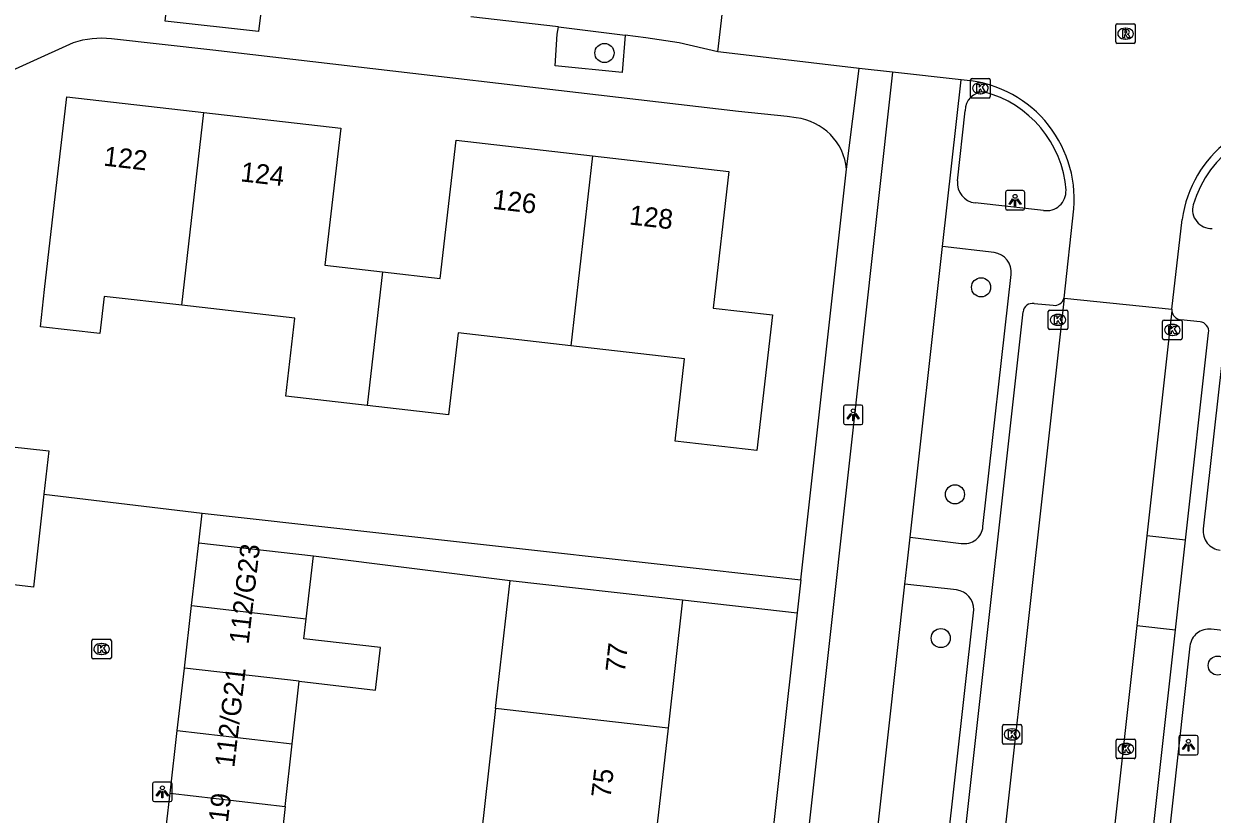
# Model space of a CAD drawing. Extents: x 162026 to 163499, y 387297 to 388169.
# Drawn here: x 162251.6 to 162312.4, y 387941.9 to 387982.3 of the extents above; entities that cross this region are included whole.
import ezdxf

# ---------------------------------------------------------------- set-up
doc = ezdxf.new("R2010")
doc.units = 0
for name, color, linetype in [('IMGEO_Boom', 7, 'Continuous'), ('IMGEO_Fietspad_gesloten', 7, 'Continuous'), ('IMGEO_Kolk', 7, 'Continuous'), ('IMGEO_Lichtpunt', 7, 'Continuous'), ('IMGEO_Pand', 7, 'Continuous'), ('IMGEO_Pand_nummerreeks', 7, 'Continuous'), ('IMGEO_Parkeervlak_open', 7, 'Continuous'), ('IMGEO_Rijbaan_lokaal_gesloten', 7, 'Continuous'), ('IMGEO_Rijbaan_lokaal_open', 7, 'Continuous'), ('IMGEO_Rioolput', 7, 'Continuous'), ('IMGEO_Voetpad_open', 7, 'Continuous')]:
    doc.layers.add(name, color=color, linetype=linetype)

msp = doc.modelspace()

# ---------------------------------------------------------------- linework, layer by layer
at = {"layer": 'IMGEO_Boom'}
for centre in [(162281.289, 387980.833), (162300.567, 387968.849), (162299.23, 387958.261), (162298.502, 387950.91), (162312.679, 387949.505)]:
    msp.add_circle(centre, 0.489, dxfattribs=at)
at = {"layer": 'IMGEO_Fietspad_gesloten'}
for points in [[(162296.034, 387979.848), (162290.464, 387929.711), (162288.097, 387908.488), (162278.956, 387826.545), (162278.87, 387825.665), (162278.372, 387825.72), (162277.589, 387818.699), (162278.067, 387818.669), (162270.183, 387748.502), (162261.381, 387669.505), (162260.87, 387664.615)], [(162298.595, 387970.931), (162299.549, 387979.456)], [(162296.932, 387956.066), (162298.595, 387970.931)], [(162296.667, 387953.66), (162296.814, 387954.996), (162296.932, 387956.066)], [(162293.703, 387926.861), (162296.667, 387953.66)]]:
    msp.add_lwpolyline(points, dxfattribs=at)
at = {"layer": 'IMGEO_Kolk'}
for p, q in [((162300.107, 387979.531), (162300.959, 387979.531)), ((162300.032, 387978.605), (162300.032, 387979.457)), ((162300.52, 387979.311), (162300.545, 387979.311)), ((162301.033, 387979.457), (162301.033, 387978.605)), ((162300.959, 387978.531), (162300.107, 387978.531)), ((162300.543, 387978.751), (162300.518, 387978.751)), ((162304.006, 387966.76), (162304.006, 387967.612)), ((162304.081, 387967.686), (162304.933, 387967.686)), ((162304.494, 387967.466), (162304.519, 387967.466)), ((162305.007, 387967.612), (162305.007, 387966.76)), ((162304.517, 387966.906), (162304.492, 387966.906)), ((162309.855, 387966.244), (162309.855, 387967.096)), ((162309.93, 387967.17), (162310.782, 387967.17)), ((162310.343, 387966.95), (162310.368, 387966.95)), ((162310.856, 387967.096), (162310.856, 387966.244)), ((162304.933, 387966.686), (162304.081, 387966.686)), ((162310.782, 387966.17), (162309.93, 387966.17)), ((162310.366, 387966.39), (162310.341, 387966.39)), ((162255.049, 387949.925), (162255.049, 387950.777)), ((162255.124, 387950.851), (162255.976, 387950.851)), ((162255.537, 387950.631), (162255.562, 387950.631)), ((162256.05, 387950.777), (162256.05, 387949.925)), ((162255.976, 387949.851), (162255.124, 387949.851)), ((162255.56, 387950.071), (162255.535, 387950.071)), ((162301.655, 387945.558), (162301.655, 387946.41)), ((162301.73, 387946.484), (162302.582, 387946.484)), ((162302.143, 387946.264), (162302.168, 387946.264)), ((162302.656, 387946.41), (162302.656, 387945.558)), ((162302.582, 387945.484), (162301.73, 387945.484)), ((162302.166, 387945.704), (162302.141, 387945.704)), ((162307.477, 387944.818), (162307.477, 387945.67)), ((162307.552, 387945.744), (162308.404, 387945.744)), ((162307.965, 387945.524), (162307.99, 387945.524)), ((162308.478, 387945.67), (162308.478, 387944.818)), ((162307.988, 387944.964), (162307.963, 387944.964)), ((162308.404, 387944.744), (162307.552, 387944.744))]:
    msp.add_line(p, q, dxfattribs=at)
for points in [[(162300.107, 387979.531), (162300.959, 387979.531)], [(162300.032, 387978.605), (162300.032, 387979.457)], [(162300.353, 387979.231), (162300.476, 387979.231), (162300.476, 387979.08), (162300.606, 387979.231), (162300.77, 387979.231), (162300.624, 387979.08), (162300.777, 387978.831), (162300.625, 387978.831), (162300.54, 387978.995), (162300.476, 387978.928), (162300.476, 387978.831), (162300.353, 387978.831), (162300.353, 387979.231)], [(162301.033, 387979.457), (162301.033, 387978.605)], [(162300.959, 387978.531), (162300.107, 387978.531)], [(162304.006, 387966.76), (162304.006, 387967.612)], [(162304.081, 387967.686), (162304.933, 387967.686)], [(162304.327, 387967.386), (162304.45, 387967.386), (162304.45, 387967.235), (162304.58, 387967.386), (162304.744, 387967.386), (162304.598, 387967.235), (162304.751, 387966.986), (162304.599, 387966.986), (162304.514, 387967.15), (162304.45, 387967.083), (162304.45, 387966.986), (162304.327, 387966.986), (162304.327, 387967.386)], [(162305.007, 387967.612), (162305.007, 387966.76)], [(162309.855, 387966.244), (162309.855, 387967.096)], [(162309.93, 387967.17), (162310.782, 387967.17)], [(162310.176, 387966.87), (162310.299, 387966.87), (162310.299, 387966.719), (162310.429, 387966.87), (162310.593, 387966.87), (162310.447, 387966.719), (162310.6, 387966.47), (162310.448, 387966.47), (162310.363, 387966.634), (162310.299, 387966.567), (162310.299, 387966.47), (162310.176, 387966.47), (162310.176, 387966.87)], [(162310.856, 387967.096), (162310.856, 387966.244)], [(162304.933, 387966.686), (162304.081, 387966.686)], [(162310.782, 387966.17), (162309.93, 387966.17)], [(162255.049, 387949.925), (162255.049, 387950.777)], [(162255.124, 387950.851), (162255.976, 387950.851)], [(162255.37, 387950.551), (162255.493, 387950.551), (162255.493, 387950.4), (162255.623, 387950.551), (162255.787, 387950.551), (162255.641, 387950.4), (162255.794, 387950.151), (162255.642, 387950.151), (162255.557, 387950.315), (162255.493, 387950.248), (162255.493, 387950.151), (162255.37, 387950.151), (162255.37, 387950.551)], [(162256.05, 387950.777), (162256.05, 387949.925)], [(162255.976, 387949.851), (162255.124, 387949.851)], [(162301.655, 387945.558), (162301.655, 387946.41)], [(162301.73, 387946.484), (162302.582, 387946.484)], [(162301.976, 387946.184), (162302.099, 387946.184), (162302.099, 387946.033), (162302.229, 387946.184), (162302.393, 387946.184), (162302.247, 387946.033), (162302.4, 387945.784), (162302.248, 387945.784), (162302.163, 387945.948), (162302.099, 387945.881), (162302.099, 387945.784), (162301.976, 387945.784), (162301.976, 387946.184)], [(162302.656, 387946.41), (162302.656, 387945.558)], [(162302.582, 387945.484), (162301.73, 387945.484)], [(162307.477, 387944.818), (162307.477, 387945.67)], [(162307.552, 387945.744), (162308.404, 387945.744)], [(162308.478, 387945.67), (162308.478, 387944.818)], [(162307.798, 387945.444), (162307.921, 387945.444), (162307.921, 387945.293), (162308.051, 387945.444), (162308.215, 387945.444), (162308.069, 387945.293), (162308.222, 387945.044), (162308.07, 387945.044), (162307.985, 387945.208), (162307.921, 387945.141), (162307.921, 387945.044), (162307.798, 387945.044), (162307.798, 387945.444)], [(162308.404, 387944.744), (162307.552, 387944.744)]]:
    msp.add_lwpolyline(points, dxfattribs=at)
for centre, start, end in [((162300.109, 387979.455), 91.55205, 178.44795), ((162300.109, 387979.455), 91.55205, 178.44795), ((162300.957, 387979.455), 1.55205, 88.44795), ((162300.957, 387979.455), 1.55205, 88.44795), ((162300.109, 387978.607), 181.55205, 268.44795), ((162300.109, 387978.607), 181.55205, 268.44795), ((162300.957, 387978.607), 271.55205, 358.44795), ((162300.957, 387978.607), 271.55205, 358.44795), ((162304.083, 387967.61), 91.55205, 178.44795), ((162304.083, 387967.61), 91.55205, 178.44795), ((162304.931, 387967.61), 1.55205, 88.44795), ((162304.931, 387967.61), 1.55205, 88.44795), ((162304.083, 387966.762), 181.55205, 268.44795), ((162304.083, 387966.762), 181.55205, 268.44795), ((162304.931, 387966.762), 271.55205, 358.44795), ((162304.931, 387966.762), 271.55205, 358.44795), ((162309.932, 387967.094), 91.55205, 178.44795), ((162309.932, 387967.094), 91.55205, 178.44795), ((162310.78, 387967.094), 1.55205, 88.44795), ((162310.78, 387967.094), 1.55205, 88.44795), ((162309.932, 387966.246), 181.55205, 268.44795), ((162309.932, 387966.246), 181.55205, 268.44795), ((162310.78, 387966.246), 271.55205, 358.44795), ((162310.78, 387966.246), 271.55205, 358.44795), ((162255.126, 387950.775), 91.55205, 178.44795), ((162255.126, 387950.775), 91.55205, 178.44795), ((162255.974, 387950.775), 1.55205, 88.44795), ((162255.974, 387950.775), 1.55205, 88.44795), ((162255.126, 387949.927), 181.55205, 268.44795), ((162255.126, 387949.927), 181.55205, 268.44795), ((162255.974, 387949.927), 271.55205, 358.44795), ((162255.974, 387949.927), 271.55205, 358.44795), ((162301.732, 387946.408), 91.55205, 178.44795), ((162301.732, 387946.408), 91.55205, 178.44795), ((162302.58, 387946.408), 1.55205, 88.44795), ((162302.58, 387946.408), 1.55205, 88.44795), ((162301.732, 387945.56), 181.55205, 268.44795), ((162301.732, 387945.56), 181.55205, 268.44795), ((162302.58, 387945.56), 271.55205, 358.44795), ((162302.58, 387945.56), 271.55205, 358.44795), ((162307.554, 387945.668), 91.55205, 178.44795), ((162307.554, 387945.668), 91.55205, 178.44795), ((162308.402, 387945.668), 1.55205, 88.44795), ((162308.402, 387945.668), 1.55205, 88.44795), ((162307.554, 387944.82), 181.55205, 268.44795), ((162307.554, 387944.82), 181.55205, 268.44795), ((162308.402, 387944.82), 271.55205, 358.44795), ((162308.402, 387944.82), 271.55205, 358.44795)]:
    msp.add_arc(centre, 0.0765, start, end, dxfattribs=at)
for centre, major_axis, ratio, start_param, end_param in [((162300.519, 387979.031), (-0.387, 0.002), 0.722429, 4.712389, 7.853982), ((162300.544, 387979.031), (-0.39, 0.002), 0.717154, 1.570796, 4.712389), ((162304.493, 387967.186), (-0.387, 0.002), 0.722429, 4.712389, 7.853982), ((162304.518, 387967.186), (-0.39, 0.002), 0.717154, 1.570796, 4.712389), ((162310.342, 387966.67), (-0.387, 0.002), 0.722429, 4.712389, 7.853982), ((162310.367, 387966.67), (-0.39, 0.002), 0.717154, 1.570796, 4.712389), ((162255.536, 387950.351), (-0.387, 0.002), 0.722429, 4.712389, 7.853982), ((162255.561, 387950.351), (-0.39, 0.002), 0.717154, 1.570796, 4.712389), ((162302.142, 387945.984), (-0.387, 0.002), 0.722429, 4.712389, 7.853982), ((162302.167, 387945.984), (-0.39, 0.002), 0.717154, 1.570796, 4.712389), ((162307.964, 387945.244), (-0.387, 0.002), 0.722429, 4.712389, 7.853982), ((162307.989, 387945.244), (-0.39, 0.002), 0.717154, 1.570796, 4.712389)]:
    msp.add_ellipse(centre, major_axis=major_axis, ratio=ratio, start_param=start_param, end_param=end_param, dxfattribs=at)
at = {"layer": 'IMGEO_Lichtpunt'}
for p, q in [((162301.809, 387973.705), (162301.809, 387972.898)), ((162301.809, 387973.705), (162301.809, 387972.898)), ((162302.711, 387973.8), (162301.903, 387973.8)), ((162302.711, 387973.8), (162301.903, 387973.8)), ((162302.805, 387972.898), (162302.805, 387973.705)), ((162302.805, 387972.898), (162302.805, 387973.705)), ((162301.903, 387972.804), (162302.711, 387972.804)), ((162301.903, 387972.804), (162302.711, 387972.804)), ((162293.524, 387962.733), (162293.524, 387961.926)), ((162293.524, 387962.733), (162293.524, 387961.926)), ((162294.426, 387962.828), (162293.618, 387962.828)), ((162294.426, 387962.828), (162293.618, 387962.828)), ((162294.52, 387961.926), (162294.52, 387962.733)), ((162294.52, 387961.926), (162294.52, 387962.733)), ((162293.618, 387961.832), (162294.426, 387961.832)), ((162293.618, 387961.832), (162294.426, 387961.832)), ((162310.682, 387945.838), (162310.682, 387945.031)), ((162310.682, 387945.838), (162310.682, 387945.031)), ((162311.584, 387945.933), (162310.776, 387945.933)), ((162311.584, 387945.933), (162310.776, 387945.933)), ((162311.678, 387945.031), (162311.678, 387945.838)), ((162311.678, 387945.031), (162311.678, 387945.838)), ((162310.776, 387944.937), (162311.584, 387944.937)), ((162310.776, 387944.937), (162311.584, 387944.937)), ((162258.164, 387943.451), (162258.164, 387942.644)), ((162258.164, 387943.451), (162258.164, 387942.644)), ((162259.066, 387943.546), (162258.258, 387943.546)), ((162259.066, 387943.546), (162258.258, 387943.546)), ((162259.16, 387942.644), (162259.16, 387943.451)), ((162259.16, 387942.644), (162259.16, 387943.451)), ((162258.258, 387942.55), (162259.066, 387942.55)), ((162258.258, 387942.55), (162259.066, 387942.55))]:
    msp.add_line(p, q, dxfattribs=at)
for points in [[(162302.183, 387973.369), (162302.222, 387973.341), (162302.034, 387973.079), (162301.996, 387973.106), (162302.183, 387973.369)], [(162302.285, 387973.321), (162302.332, 387973.321), (162302.332, 387972.999), (162302.285, 387972.999), (162302.285, 387973.321)], [(162302.395, 387973.341), (162302.433, 387973.368), (162302.62, 387973.106), (162302.581, 387973.078), (162302.395, 387973.341)], [(162293.898, 387962.397), (162293.937, 387962.369), (162293.749, 387962.107), (162293.711, 387962.134), (162293.898, 387962.397)], [(162294, 387962.349), (162294.047, 387962.349), (162294.047, 387962.027), (162294, 387962.027), (162294, 387962.349)], [(162294.11, 387962.369), (162294.148, 387962.396), (162294.335, 387962.134), (162294.296, 387962.106), (162294.11, 387962.369)], [(162311.056, 387945.502), (162311.095, 387945.474), (162310.907, 387945.212), (162310.869, 387945.239), (162311.056, 387945.502)], [(162311.158, 387945.454), (162311.205, 387945.454), (162311.205, 387945.132), (162311.158, 387945.132), (162311.158, 387945.454)], [(162311.268, 387945.474), (162311.306, 387945.501), (162311.493, 387945.239), (162311.454, 387945.211), (162311.268, 387945.474)], [(162258.538, 387943.115), (162258.577, 387943.087), (162258.389, 387942.825), (162258.351, 387942.852), (162258.538, 387943.115)], [(162258.64, 387943.067), (162258.687, 387943.067), (162258.687, 387942.745), (162258.64, 387942.745), (162258.64, 387943.067)], [(162258.75, 387943.087), (162258.788, 387943.114), (162258.975, 387942.852), (162258.936, 387942.824), (162258.75, 387943.087)]]:
    msp.add_lwpolyline(points, dxfattribs=at)
for centre in [(162302.308, 387973.503), (162294.023, 387962.531), (162311.181, 387945.636), (162258.663, 387943.249)]:
    msp.add_circle(centre, 0.0994, dxfattribs=at)
for centre, start, end in [((162301.903, 387973.705), 90, 180), ((162301.903, 387973.705), 90, 180), ((162302.711, 387973.705), 0, 90), ((162302.711, 387973.705), 0, 90), ((162301.903, 387972.898), 180, 270), ((162301.903, 387972.898), 180, 270), ((162302.711, 387972.898), 270, 0), ((162302.711, 387972.898), 270, 360), ((162293.618, 387962.733), 90, 180), ((162293.618, 387962.733), 90, 180), ((162294.426, 387962.733), 0, 90), ((162294.426, 387962.733), 0, 90), ((162293.618, 387961.926), 180, 270), ((162293.618, 387961.926), 180, 270), ((162294.426, 387961.926), 270, 0), ((162294.426, 387961.926), 270, 360), ((162310.776, 387945.838), 90, 180), ((162310.776, 387945.838), 90, 180), ((162311.584, 387945.838), 0, 90), ((162311.584, 387945.838), 0, 90), ((162310.776, 387945.031), 180, 270), ((162310.776, 387945.031), 180, 270), ((162311.584, 387945.031), 270, 0), ((162311.584, 387945.031), 270, 360), ((162258.258, 387943.451), 90, 180), ((162258.258, 387943.451), 90, 180), ((162259.066, 387943.451), 0, 90), ((162259.066, 387943.451), 0, 90), ((162258.258, 387942.644), 180, 270), ((162258.258, 387942.644), 180, 270), ((162259.066, 387942.644), 270, 0), ((162259.066, 387942.644), 270, 360)]:
    msp.add_arc(centre, 0.0946, start, end, dxfattribs=at)
at = {"layer": 'IMGEO_Pand'}
for points in [[(162259.65, 387967.93), (162255.684, 387968.384), (162255.467, 387966.486), (162252.418, 387966.835), (162252.635, 387968.733), (162253.195, 387973.623), (162253.763, 387978.59), (162260.778, 387977.787)], [(162259.65, 387967.93), (162260.778, 387977.787)], [(162260.778, 387977.787), (162267.788, 387976.985), (162266.985, 387969.975), (162269.935, 387969.637)], [(162269.935, 387969.637), (162272.883, 387969.3), (162273.693, 387976.378), (162280.678, 387975.578)], [(162280.678, 387975.578), (162287.661, 387974.779), (162286.86, 387967.781), (162289.888, 387967.434), (162289.095, 387960.507), (162284.908, 387960.986), (162285.39, 387965.195), (162279.564, 387965.862)], [(162280.678, 387975.578), (162279.564, 387965.862)], [(162269.935, 387969.637), (162269.152, 387962.798)], [(162269.152, 387962.798), (162264.977, 387963.276), (162265.434, 387967.268), (162259.65, 387967.93)], [(162279.564, 387965.862), (162273.794, 387966.523), (162273.313, 387962.322), (162269.152, 387962.798)], [(162248.918, 387960.92), (162252.845, 387960.481), (162252.599, 387958.276)], [(162252.599, 387958.276), (162252.068, 387953.523), (162250.767, 387953.668)], [(162260.159, 387952.575), (162260.527, 387955.775)], [(162260.527, 387955.775), (162266.39, 387955.112)], [(162266.027, 387951.901), (162266.39, 387955.112)], [(162275.717, 387947.306), (162276.462, 387953.862)], [(162276.462, 387953.862), (162285.289, 387952.859)], [(162285.289, 387952.859), (162284.544, 387946.302)], [(162259.791, 387949.376), (162260.159, 387952.575)], [(162260.159, 387952.575), (162266.027, 387951.901)], [(162265.666, 387948.7), (162269.574, 387948.25), (162269.819, 387950.423), (162265.91, 387950.864), (162266.027, 387951.901)], [(162259.424, 387946.176), (162259.791, 387949.376)], [(162265.666, 387948.7), (162259.791, 387949.376)], [(162265.305, 387945.5), (162265.666, 387948.7)], [(162275.717, 387947.306), (162274.992, 387940.928)], [(162284.544, 387946.302), (162275.717, 387947.306)], [(162259.056, 387942.976), (162259.424, 387946.176)], [(162259.424, 387946.176), (162265.305, 387945.5)], [(162284.544, 387946.302), (162283.819, 387939.923)], [(162264.943, 387942.299), (162265.305, 387945.5)], [(162258.688, 387939.776), (162259.056, 387942.976)], [(162259.056, 387942.976), (162264.943, 387942.299)], [(162264.943, 387942.299), (162264.582, 387939.099)]]:
    msp.add_lwpolyline(points, dxfattribs=at)
at = {"layer": 'IMGEO_Parkeervlak_open'}
msp.add_lwpolyline([(162278.942, 387982.168), (162282.345, 387981.742)], dxfattribs=at)
at = {"layer": 'IMGEO_Rijbaan_lokaal_gesloten'}
for points in [[(162287.087, 387980.885), (162287.36, 387983.225)], [(162294.331, 387980.045), (162287.244, 387980.867), (162287.087, 387980.885)], [(162296.034, 387979.848), (162294.331, 387980.045)], [(162299.549, 387979.456), (162296.034, 387979.848)], [(162304.811, 387968.292), (162305.312, 387972.855)], [(162310.334, 387967.724), (162310.861, 387972.324)], [(162304.811, 387968.292), (162296.246, 387891.427), (162293.541, 387866.933)], [(162304.811, 387968.292), (162310.334, 387967.724)], [(162310.325, 387967.647), (162309.047, 387956.134)], [(162310.334, 387967.724), (162310.325, 387967.647)], [(162309.047, 387956.134), (162308.539, 387951.558)], [(162308.539, 387951.558), (162302.841, 387900.241), (162299.054, 387866.158)]]:
    msp.add_lwpolyline(points, dxfattribs=at)
for centre, radius, start, end in [((162299.225, 387973.357), 6.108, 355.289, 86.95614), ((162316.878, 387971.502), 6.073, 82.82678, 172.21962)]:
    msp.add_arc(centre, radius, start, end, dxfattribs=at)
at = {"layer": 'IMGEO_Rijbaan_lokaal_open'}
for points in [[(162252.599, 387958.276), (162260.704, 387957.306)], [(162260.527, 387955.775), (162260.704, 387957.306)]]:
    msp.add_lwpolyline(points, dxfattribs=at)
at = {"layer": 'IMGEO_Rioolput'}
for p, q in [((162307.461, 387981.397), (162307.461, 387982.249)), ((162307.536, 387982.323), (162308.388, 387982.323)), ((162307.949, 387982.103), (162307.974, 387982.103)), ((162308.462, 387982.249), (162308.462, 387981.397)), ((162307.972, 387981.543), (162307.947, 387981.543)), ((162308.388, 387981.323), (162307.536, 387981.323))]:
    msp.add_line(p, q, dxfattribs=at)
for points in [[(162307.461, 387981.397), (162307.461, 387982.249)], [(162307.536, 387982.323), (162308.388, 387982.323)], [(162308.05, 387982.021), (162307.798, 387982.023), (162307.798, 387981.623)], [(162308.462, 387982.249), (162308.462, 387981.397)], [(162307.798, 387981.623), (162307.922, 387981.623), (162307.922, 387981.785), (162307.933, 387981.785)], [(162307.976, 387981.942), (162307.922, 387981.942), (162307.922, 387981.861)], [(162307.922, 387981.861), (162307.974, 387981.861)], [(162307.98, 387981.756), (162308.051, 387981.623), (162308.191, 387981.623), (162308.126, 387981.749)], [(162308.388, 387981.323), (162307.536, 387981.323)]]:
    msp.add_lwpolyline(points, dxfattribs=at)
for centre, radius, start, end in [((162307.538, 387982.247), 0.0765, 91.55205, 178.44795), ((162307.538, 387982.247), 0.0765, 91.55205, 178.44795), ((162308.049, 387981.911), 0.109, 350.36119, 89.41601), ((162308.386, 387982.247), 0.0765, 1.55205, 88.44795), ((162308.386, 387982.247), 0.0765, 1.55205, 88.44795), ((162307.538, 387981.399), 0.0765, 181.55205, 268.44795), ((162307.538, 387981.399), 0.0765, 181.55205, 268.44795), ((162307.932, 387981.732), 0.0533, 26.02933, 88.69889), ((162307.958, 387982.05), 0.19, 274.7715, 282.96867), ((162307.982, 387981.846), 0.0964, 77.00612, 93.18647), ((162307.996, 387981.903), 0.0378, 276.66336, 79.67722), ((162308.047, 387981.911), 0.112, 277.58423, 350.98172), ((162308.031, 387981.696), 0.108, 29.51342, 73.79051), ((162308.386, 387981.399), 0.0765, 271.55205, 358.44795), ((162308.386, 387981.399), 0.0765, 271.55205, 358.44795)]:
    msp.add_arc(centre, radius, start, end, dxfattribs=at)
for centre, major_axis, ratio, start_param, end_param in [((162307.948, 387981.823), (-0.387, 0.002), 0.722429, 4.712389, 7.853982), ((162307.973, 387981.823), (-0.39, 0.002), 0.717154, 1.570796, 4.712389)]:
    msp.add_ellipse(centre, major_axis=major_axis, ratio=ratio, start_param=start_param, end_param=end_param, dxfattribs=at)
at = {"layer": 'IMGEO_Voetpad_open'}
for points in [[(162263.824, 387983.889), (162263.585, 387981.924), (162258.806, 387982.466), (162259.028, 387984.445)], [(162278.942, 387982.168), (162274.447, 387982.68)], [(162282.345, 387981.742), (162282.19, 387979.834), (162278.769, 387980.18), (162278.868, 387981.798), (162278.942, 387982.168)], [(162254.101, 387981.349), (162240.014, 387974.97), (162211.554, 387962.659)], [(162291.097, 387977.515), (162290.634, 387977.587), (162288.142, 387977.833), (162261.241, 387980.973), (162256.056, 387981.553)], [(162287.087, 387980.885), (162285.117, 387981.352), (162283.404, 387981.609), (162282.345, 387981.742)], [(162293.685, 387974.891), (162294.331, 387980.045)], [(162299.356, 387974.287), (162299.746, 387977.882)], [(162291.341, 387953.887), (162293.685, 387974.891)], [(162303.759, 387972.782), (162300.263, 387973.168)], [(162301.234, 387970.629), (162298.595, 387970.931)], [(162300.663, 387956.611), (162302.1, 387969.506)], [(162303.277, 387968.016), (162304.263, 387967.93)], [(162313.271, 387968.348), (162311.936, 387956.502)], [(162291.572, 387867.15), (162294.303, 387892.007), (162302.723, 387967.594)], [(162311.777, 387967.088), (162310.787, 387967.188)], [(162311.038, 387955.913), (162312.212, 387966.528)], [(162260.704, 387957.306), (162291.341, 387953.887)], [(162296.932, 387956.066), (162299.551, 387955.754)], [(162311.038, 387955.913), (162309.047, 387956.134)], [(162310.512, 387951.338), (162311.038, 387955.913)], [(162266.39, 387955.112), (162276.462, 387953.862)], [(162291.341, 387953.887), (162291.153, 387952.205)], [(162299.304, 387953.372), (162296.667, 387953.66)], [(162285.289, 387952.859), (162291.153, 387952.205)], [(162291.153, 387952.205), (162285.089, 387897.861), (162281.859, 387868.778)], [(162297.414, 387927.451), (162300.19, 387952.357)], [(162308.539, 387951.558), (162310.512, 387951.338)], [(162301.044, 387865.937), (162304.798, 387900.046), (162310.512, 387951.338)], [(162314.601, 387951.117), (162312.346, 387951.368)], [(162311.258, 387950.502), (162308.62, 387926.723)]]:
    msp.add_lwpolyline(points, dxfattribs=at)
for centre, radius, start, end in [((162255.512, 387977.3), 4.287, 82.70487, 109.2094), ((162300.712, 387977.877), 0.966, 90.04797, 179.71404), ((162299.303, 387973.395), 5.628, 4.34604, 75.50706), ((162290.771, 387974.605), 2.928, 5.60558, 83.60293), ((162316.871, 387971.493), 5.666, 84.10023, 163.84859), ((162300.383, 387974.192), 1.031, 174.72237, 263.33029), ((162303.915, 387973.77), 1, 261.0367, 2.91031), ((162312.342, 387972.812), 0.95, 164.30937, 273.35732), ((162301.092, 387969.624), 1.015, 353.31527, 81.95986), ((162303.186, 387967.561), 0.464, 78.70223, 175.89321), ((162304.333, 387968.419), 0.494, 261.80831, 345.08791), ((162310.852, 387967.716), 0.532, 187.42105, 262.95221), ((162311.723, 387966.597), 0.494, 351.93634, 83.74276), ((162299.706, 387956.703), 0.962, 260.74136, 354.50033), ((162312.922, 387956.392), 0.992, 173.61961, 263.64898), ((162299.203, 387952.39), 0.987, 358.08752, 84.14831), ((162312.233, 387950.393), 0.981, 83.40844, 173.62804)]:
    msp.add_arc(centre, radius, start, end, dxfattribs=at)

# ---------------------------------------------------------------- texts
at = {"layer": 'IMGEO_Pand_nummerreeks'}
for s, rotation, p in [('122', 353.47401, (162255.615, 387975.077)), ('124', 353.47156, (162262.63, 387974.274)), ('126', 353.46944, (162275.533, 387972.866)), ('128', 353.46944, (162282.521, 387972.067)), ('112/G23', 83.37525, (162263.073, 387950.569)), ('77', 83.51597, (162282.328, 387949.115)), ('112/G21', 83.37525, (162262.341, 387944.265)), ('75', 83.51597, (162281.599, 387942.7)), ('112/G19', 83.37525, (162261.593, 387937.828))]:
    msp.add_text(s, height=1, rotation=rotation, dxfattribs=at).set_placement(p)

doc.saveas('drawing.dxf')
